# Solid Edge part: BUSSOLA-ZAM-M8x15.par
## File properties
Title: 1340000890
Subject: Bussola zama M8x15 esagono inc.
Author: v_lucarelli
Comments: MBUZAA3M5 ZINC.
Template: Zama.par
Last saved by: v_lucarelli
Revision: 12
Application: Solid Edge
Tipo di contenuto documento: 0
Material: Zama
Company: EFFEBI S.p.A.
custom2: 2001-08-01
DIMENSIONI: .
Densità: 6000,000 kg/m^3
Precisione: 0,99
Document Number: Commerciale
Project Name: Commerciale
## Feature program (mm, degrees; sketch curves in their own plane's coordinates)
sketch for "ExtrudedProtrusion_1" plane through (0, 0, 0) normal (0, 0, 1) x-axis (1, 0, 0)
  circle centre (0, 0) radius 5
extrude "ExtrudedProtrusion_1" add finite 12 symmetric
sketch for "ExtrudedProtrusion_2" plane through (0, 0, 6) normal (0, 0, 1) x-axis (0, 1, 0)
  circle centre (0, 0) radius 7
extrude "ExtrudedProtrusion_2" add finite 3 along +normal
chamfer "unnamed Chamfer 1"
chamfer "Chamfer_2" setback 0.5
helix protrusion "HelixProtrusion_1"  Pitch = 3 mm; NumberOfTurns = 3.5; Precisione = 1
sketch for "unnamed Cutout 1" plane through (0, 0, 9) normal (0, 0, 1) x-axis (1, 0, 0)
  line (-4.6188, 0) -> (-2.3094, 4)
  line (-2.3094, 4) -> (2.3094, 4)
  line (2.3094, 4) -> (4.6188, 0)
  line (4.6188, 0) -> (2.3094, -4)
  line (2.3094, -4) -> (-2.3094, -4)
  line (-2.3094, -4) -> (-4.6188, 0)
extrude "unnamed Cutout 1" cut finite 3.5 along -normal
sketch for "Foro_1" plane through (0, 0, 5.5) normal (0, 0, 1) x-axis (-0.5, 0.866025, 0)
hole "Foro_1" through  ThreadDepth = 2 mm
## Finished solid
Body 1: solid body, 19 faces, 39 edges, 22 vertices.
  Faces by surface: plane 12, cylinder 3, cone 2, spline 2
  Edges by curve: line 24, circle 7, curve on surface 5, intersection 2, spline 1
Bounding box of the edges (mm; curved faces can reach further): 14.000 x 14.000 x 15.000, from (-7, -7, -6) to (7, 7, 9).
Cylindrical faces by radius (mm): R3.3235 x1, R5 x1, R7 x1
Conical faces (half-angle, radius in mm at the cone's reference point): 45 deg R4.5 x1, 45 deg R5.1 x1
Planar faces by outward normal: +y 1, +z 2, -x 2, -y 1, -z 2, oblique 4
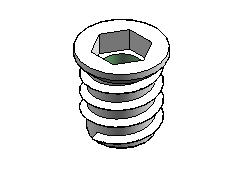
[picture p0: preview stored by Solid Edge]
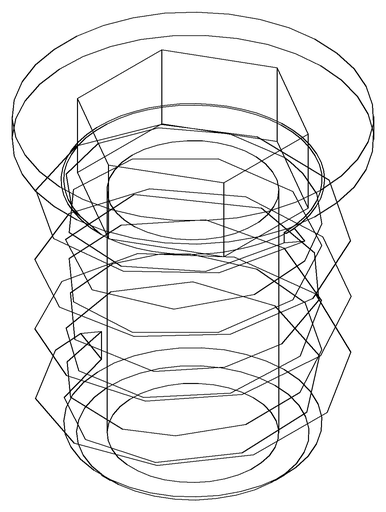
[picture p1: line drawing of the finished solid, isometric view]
